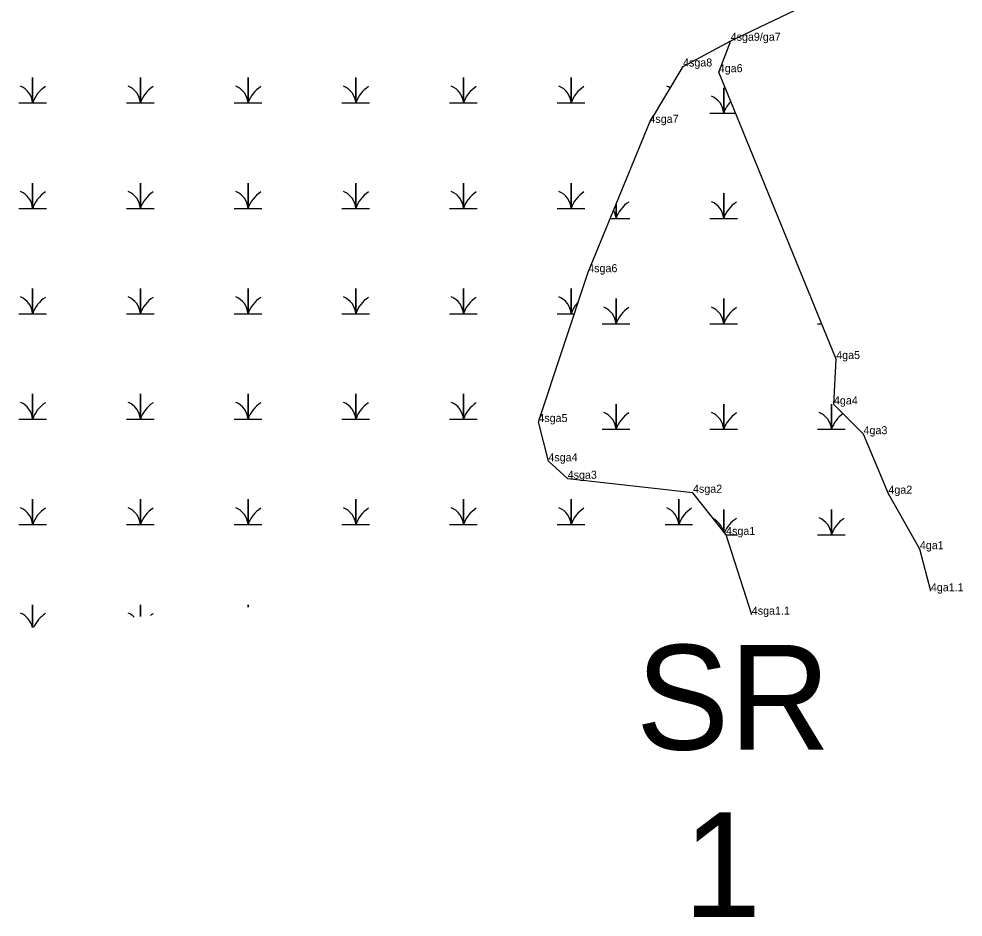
# Model space of a CAD drawing. Extents: x 2072529 to 2268796, y 436423 to 470406.
# Drawn here: x 2105482 to 2106072, y 455709 to 456270 of the extents above; entities that cross this region are included whole.
import ezdxf

# ---------------------------------------------------------------- set-up
doc = ezdxf.new("R2010")
doc.units = 0
for name, color, linetype in [('Default', 7, 'Continuous'), ('Exist Environmental Wetland Boundary', 7, 'Continuous'), ('Exist Environmental Wetland Boundary Cogo Comment', 7, 'Continuous'), ('Exist Hydro Jurisdictional Stream or Body of Water NEU Mitigable', 7, 'Continuous'), ('Exist Hydro Jurisdictional Stream or Body of Water NEU Mitigable Cogo Comment', 7, 'Continuous'), ('Exist Hydro Swamp or Marsh', 7, 'Continuous'), ('Old_Level_20', 7, 'Continuous')]:
    doc.layers.add(name, color=color, linetype=linetype)

msp = doc.modelspace()

# ---------------------------------------------------------------- linework, layer by layer
at = {"layer": 'Exist Environmental Wetland Boundary'}
msp.add_lwpolyline([(2106051.8, 455912.41), (2106044.92, 455938.66), (2106025.27, 455973.29), (2106009.75, 456010.43), (2105991.25, 456029.05), (2105992.67, 456057.36), (2105919.34, 456236.39), (2105926.77, 456256)], dxfattribs=at)
at = {"layer": 'Exist Hydro Jurisdictional Stream or Body of Water NEU Mitigable'}
msp.add_lwpolyline([(2105939.94, 455897.77), (2105923.9, 455947.53), (2105903.24, 455973.88), (2105824.98, 455982.61), (2105812.94, 455993.51), (2105806.67, 456018.05), (2105837.8, 456111.54), (2105876.03, 456204.78), (2105897.03, 456239.95), (2105926.77, 456256), (2105976.18, 456279.56), (2106062.28, 456297.21)], dxfattribs=at)
at = {"layer": 'Exist Hydro Swamp or Marsh'}
for points in [[(2105482.26, 456217.21), (2105490.86, 456217.21), (2105490.86, 456232.99), (2105490.86, 456217.21), (2105499.47, 456217.21)], [(2105549.51, 456217.21), (2105558.11, 456217.21), (2105558.11, 456232.99), (2105558.11, 456217.21), (2105566.72, 456217.21)], [(2105616.76, 456217.21), (2105625.36, 456217.21), (2105625.36, 456232.99), (2105625.36, 456217.21), (2105633.97, 456217.21)], [(2105684.01, 456217.21), (2105692.61, 456217.21), (2105692.61, 456232.99), (2105692.61, 456217.21), (2105701.22, 456217.21)], [(2105751.26, 456217.21), (2105759.86, 456217.21), (2105759.86, 456232.99), (2105759.86, 456217.21), (2105768.47, 456217.21)], [(2105818.51, 456217.21), (2105827.11, 456217.21), (2105827.11, 456232.99), (2105827.11, 456217.21), (2105835.72, 456217.21)], [(2105913.81, 456210.88), (2105922.41, 456210.88), (2105922.41, 456226.66), (2105922.41, 456210.88), (2105929.79, 456210.88)], [(2105482.26, 456151.41), (2105490.86, 456151.41), (2105490.86, 456167.19), (2105490.86, 456151.41), (2105499.47, 456151.41)], [(2105549.51, 456151.41), (2105558.11, 456151.41), (2105558.11, 456167.19), (2105558.11, 456151.41), (2105566.72, 456151.41)], [(2105616.76, 456151.41), (2105625.36, 456151.41), (2105625.36, 456167.19), (2105625.36, 456151.41), (2105633.97, 456151.41)], [(2105684.01, 456151.41), (2105692.61, 456151.41), (2105692.61, 456167.19), (2105692.61, 456151.41), (2105701.22, 456151.41)], [(2105751.26, 456151.41), (2105759.86, 456151.41), (2105759.86, 456167.19), (2105759.86, 456151.41), (2105768.47, 456151.41)], [(2105818.51, 456151.41), (2105827.11, 456151.41), (2105827.11, 456167.19), (2105827.11, 456151.41), (2105835.72, 456151.41)], [(2105913.81, 456145.08), (2105922.41, 456145.08), (2105922.41, 456160.86), (2105922.41, 456145.08), (2105931.01, 456145.08)], [(2105851.55, 456145.08), (2105855.16, 456145.08), (2105855.16, 456153.89)], [(2105855.16, 456153.89), (2105855.16, 456145.08), (2105863.76, 456145.08)], [(2105482.26, 456085.61), (2105490.86, 456085.61), (2105490.86, 456101.39), (2105490.86, 456085.61), (2105499.47, 456085.61)], [(2105549.51, 456085.61), (2105558.11, 456085.61), (2105558.11, 456101.39), (2105558.11, 456085.61), (2105566.72, 456085.61)], [(2105616.76, 456085.61), (2105625.36, 456085.61), (2105625.36, 456101.39), (2105625.36, 456085.61), (2105633.97, 456085.61)], [(2105684.01, 456085.61), (2105692.61, 456085.61), (2105692.61, 456101.39), (2105692.61, 456085.61), (2105701.22, 456085.61)], [(2105751.26, 456085.61), (2105759.86, 456085.61), (2105759.86, 456101.39), (2105759.86, 456085.61), (2105768.47, 456085.61)], [(2105818.51, 456085.61), (2105827.11, 456085.61), (2105827.11, 456101.39), (2105827.11, 456085.61), (2105829.16, 456085.61)], [(2105846.56, 456079.28), (2105855.16, 456079.28), (2105855.16, 456095.06), (2105855.16, 456079.28), (2105863.76, 456079.28)], [(2105913.81, 456079.28), (2105922.41, 456079.28), (2105922.41, 456095.06), (2105922.41, 456079.28), (2105931.01, 456079.28)], [(2105981.06, 456079.28), (2105983.69, 456079.28)], [(2105482.26, 456019.81), (2105490.86, 456019.81), (2105490.86, 456035.59), (2105490.86, 456019.81), (2105499.47, 456019.81)], [(2105549.51, 456019.81), (2105558.11, 456019.81), (2105558.11, 456035.59), (2105558.11, 456019.81), (2105566.72, 456019.81)], [(2105616.76, 456019.81), (2105625.36, 456019.81), (2105625.36, 456035.59), (2105625.36, 456019.81), (2105633.97, 456019.81)], [(2105684.01, 456019.81), (2105692.61, 456019.81), (2105692.61, 456035.59), (2105692.61, 456019.81), (2105701.22, 456019.81)], [(2105751.26, 456019.81), (2105759.86, 456019.81), (2105759.86, 456035.59), (2105759.86, 456019.81), (2105768.47, 456019.81)], [(2105846.56, 456013.48), (2105855.16, 456013.48), (2105855.16, 456029.26), (2105855.16, 456013.48), (2105863.76, 456013.48)], [(2105913.81, 456013.48), (2105922.41, 456013.48), (2105922.41, 456029.26), (2105922.41, 456013.48), (2105931.01, 456013.48)], [(2105981.06, 456013.48), (2105989.66, 456013.48), (2105989.66, 456029.26), (2105989.66, 456013.48), (2105998.26, 456013.48)], [(2105482.26, 455954.01), (2105490.86, 455954.01), (2105490.86, 455969.79), (2105490.86, 455954.01), (2105499.47, 455954.01)], [(2105549.51, 455954.01), (2105558.11, 455954.01), (2105558.11, 455969.79), (2105558.11, 455954.01), (2105566.72, 455954.01)], [(2105616.76, 455954.01), (2105625.36, 455954.01), (2105625.36, 455969.79), (2105625.36, 455954.01), (2105633.97, 455954.01)], [(2105684.01, 455954.01), (2105692.61, 455954.01), (2105692.61, 455969.79), (2105692.61, 455954.01), (2105701.22, 455954.01)], [(2105751.26, 455954.01), (2105759.86, 455954.01), (2105759.86, 455969.79), (2105759.86, 455954.01), (2105768.47, 455954.01)], [(2105818.51, 455954.01), (2105827.11, 455954.01), (2105827.11, 455969.79), (2105827.11, 455954.01), (2105835.72, 455954.01)], [(2105885.76, 455954.01), (2105894.36, 455954.01), (2105894.36, 455969.79), (2105894.36, 455954.01), (2105902.97, 455954.01)], [(2105922.41, 455949.43), (2105922.41, 455963.46), (2105922.41, 455949.43)], [(2105981.06, 455947.68), (2105989.66, 455947.68), (2105989.66, 455963.46), (2105989.66, 455947.68), (2105998.26, 455947.68)], [(2105923.78, 455947.68), (2105931.01, 455947.68)], [(2105490.86, 455889.74), (2105490.86, 455903.99), (2105490.86, 455889.74)], [(2105558.11, 455896.67), (2105558.11, 455903.99), (2105558.11, 455896.67)], [(2105625.36, 455902.54), (2105625.36, 455903.99), (2105625.36, 455902.54)]]:
    msp.add_lwpolyline(points, dxfattribs=at)
for centre, radius, start, end in [((2105478.6, 456216.32), 12.3, 4.14034, 67.53497), ((2105509.11, 456211.15), 19.22, 122.12745, 161.62219), ((2105545.85, 456216.32), 12.3, 4.14034, 67.53497), ((2105576.36, 456211.15), 19.22, 122.12745, 161.62219), ((2105613.1, 456216.32), 12.3, 4.14034, 67.53497), ((2105643.61, 456211.15), 19.22, 122.12745, 161.62219), ((2105680.35, 456216.32), 12.3, 4.14034, 67.53497), ((2105710.86, 456211.15), 19.22, 122.12745, 161.62219), ((2105747.6, 456216.32), 12.3, 4.14034, 67.53497), ((2105778.11, 456211.15), 19.22, 122.12745, 161.62219), ((2105814.85, 456216.32), 12.3, 4.14034, 67.53497), ((2105845.36, 456211.15), 19.22, 122.12745, 161.62219), ((2105882.1, 456216.32), 12.3, 55.8807, 67.53497), ((2105910.15, 456209.99), 12.3, 4.14034, 67.53497), ((2105940.66, 456204.82), 19.22, 136.07388, 161.62219), ((2105478.6, 456150.52), 12.3, 4.14034, 67.53497), ((2105509.11, 456145.35), 19.22, 122.12745, 161.62219), ((2105545.85, 456150.52), 12.3, 4.14034, 67.53497), ((2105576.36, 456145.35), 19.22, 122.12745, 161.62219), ((2105613.1, 456150.52), 12.3, 4.14034, 67.53497), ((2105643.61, 456145.35), 19.22, 122.12745, 161.62219), ((2105680.35, 456150.52), 12.3, 4.14034, 67.53497), ((2105710.86, 456145.35), 19.22, 122.12745, 161.62219), ((2105747.6, 456150.52), 12.3, 4.14034, 67.53497), ((2105778.11, 456145.35), 19.22, 122.12745, 161.62219), ((2105814.85, 456150.52), 12.3, 4.14034, 67.53497), ((2105845.36, 456145.35), 19.22, 122.12745, 161.62219), ((2105873.41, 456139.02), 19.22, 122.12745, 161.62219), ((2105910.15, 456144.19), 12.3, 4.14034, 67.53497), ((2105940.66, 456139.02), 19.22, 122.12745, 161.62219), ((2105842.9, 456144.19), 12.3, 4.14034, 29.12355), ((2105478.6, 456084.72), 12.3, 4.14034, 67.53497), ((2105509.11, 456079.55), 19.22, 122.12745, 161.62219), ((2105545.85, 456084.72), 12.3, 4.14034, 67.53497), ((2105576.36, 456079.55), 19.22, 122.12745, 161.62219), ((2105613.1, 456084.72), 12.3, 4.14034, 67.53497), ((2105643.61, 456079.55), 19.22, 122.12745, 161.62219), ((2105680.35, 456084.72), 12.3, 4.14034, 67.53497), ((2105710.86, 456079.55), 19.22, 122.12745, 161.62219), ((2105747.6, 456084.72), 12.3, 4.14034, 67.53497), ((2105778.11, 456079.55), 19.22, 122.12745, 161.62219), ((2105814.85, 456084.72), 12.3, 4.14034, 67.53497), ((2105845.36, 456079.55), 19.22, 135.59604, 161.62219), ((2105842.9, 456078.39), 12.3, 4.14034, 67.53497), ((2105873.41, 456073.22), 19.22, 122.12745, 161.62219), ((2105910.15, 456078.39), 12.3, 4.14034, 67.53497), ((2105940.66, 456073.22), 19.22, 122.12745, 161.62219), ((2105478.6, 456018.92), 12.3, 4.14034, 67.53497), ((2105509.11, 456013.75), 19.22, 122.12745, 161.62219), ((2105545.85, 456018.92), 12.3, 4.14034, 67.53497), ((2105576.36, 456013.75), 19.22, 122.12745, 161.62219), ((2105613.1, 456018.92), 12.3, 4.14034, 67.53497), ((2105643.61, 456013.75), 19.22, 122.12745, 161.62219), ((2105680.35, 456018.92), 12.3, 4.14034, 67.53497), ((2105710.86, 456013.75), 19.22, 122.12745, 161.62219), ((2105747.6, 456018.92), 12.3, 4.14034, 67.53497), ((2105778.11, 456013.75), 19.22, 122.12745, 161.62219), ((2105842.9, 456012.59), 12.3, 4.14034, 67.53497), ((2105873.41, 456007.42), 19.22, 122.12745, 161.62219), ((2105910.15, 456012.59), 12.3, 4.14034, 67.53497), ((2105940.66, 456007.42), 19.22, 122.12745, 161.62219), ((2105977.4, 456012.59), 12.3, 4.14034, 67.53497), ((2106007.91, 456007.42), 19.22, 124.52348, 161.62219), ((2105478.6, 455953.12), 12.3, 4.14034, 67.53497), ((2105509.11, 455947.95), 19.22, 122.12745, 161.62219), ((2105545.85, 455953.12), 12.3, 4.14034, 67.53497), ((2105576.36, 455947.95), 19.22, 122.12745, 161.62219), ((2105613.1, 455953.12), 12.3, 4.14034, 67.53497), ((2105643.61, 455947.95), 19.22, 122.12745, 161.62219), ((2105680.35, 455953.12), 12.3, 4.14034, 67.53497), ((2105710.86, 455947.95), 19.22, 122.12745, 161.62219), ((2105747.6, 455953.12), 12.3, 4.14034, 67.53497), ((2105778.11, 455947.95), 19.22, 122.12745, 161.62219), ((2105814.85, 455953.12), 12.3, 4.14034, 67.53497), ((2105845.36, 455947.95), 19.22, 122.12745, 161.62219), ((2105882.1, 455953.12), 12.3, 4.14034, 67.53497), ((2105912.61, 455947.95), 19.22, 122.12745, 161.62219), ((2105910.15, 455946.79), 12.3, 14.60347, 61.57684), ((2105940.66, 455941.62), 19.22, 122.12745, 157.84839), ((2105977.4, 455946.79), 12.3, 4.14034, 67.53497), ((2106007.91, 455941.62), 19.22, 122.12745, 161.62219), ((2105478.6, 455887.32), 12.3, 11.25454, 67.53497), ((2105545.85, 455887.32), 12.3, 46.72062, 67.53497), ((2105509.11, 455882.15), 19.22, 122.12745, 156.52673), ((2105576.36, 455882.15), 19.22, 122.12745, 128.13164)]:
    msp.add_arc(centre, radius, start, end, dxfattribs=at)
at = {"layer": 'Old_Level_20'}
for p, q in [((2105926.77, 456256), (2105926.77, 456256)), ((2105926.77, 456256), (2105926.77, 456256)), ((2105897.03, 456239.95), (2105897.03, 456239.95)), ((2105919.34, 456236.39), (2105919.34, 456236.39)), ((2105876.03, 456204.78), (2105876.03, 456204.78)), ((2105837.8, 456111.54), (2105837.8, 456111.54)), ((2105992.67, 456057.36), (2105992.67, 456057.36)), ((2105991.25, 456029.05), (2105991.25, 456029.05)), ((2105806.67, 456018.05), (2105806.67, 456018.05)), ((2106009.75, 456010.43), (2106009.75, 456010.43)), ((2105812.94, 455993.51), (2105812.94, 455993.51)), ((2105824.98, 455982.61), (2105824.98, 455982.61)), ((2105903.24, 455973.88), (2105903.24, 455973.88)), ((2106025.27, 455973.29), (2106025.27, 455973.29)), ((2105923.9, 455947.53), (2105923.9, 455947.53)), ((2106044.92, 455938.66), (2106044.92, 455938.66)), ((2106051.8, 455912.41), (2106051.8, 455912.41)), ((2105939.94, 455897.77), (2105939.94, 455897.77)), ((2105939.94, 455897.77), (2105939.94, 455897.77)), ((2105939.94, 455897.77), (2105939.94, 455897.77))]:
    msp.add_line(p, q, dxfattribs=at)

# ---------------------------------------------------------------- texts
at = {"layer": 'Default'}
for s, p in [('SR', (2105867.61, 455813.54)), ('1', (2105897.17, 455709))]:
    msp.add_text(s, height=65.34, dxfattribs=at).set_placement(p)
at = {"layer": 'Exist Environmental Wetland Boundary Cogo Comment'}
for s, p in [('4ga5', (2105992.67, 456057.36)), ('4ga4', (2105991.25, 456029.05)), ('4ga3', (2106009.75, 456010.43)), ('4ga2', (2106025.27, 455973.29)), ('4ga1', (2106044.92, 455938.66)), ('4ga1.1', (2106051.8, 455912.41))]:
    msp.add_text(s, height=5, dxfattribs=at).set_placement(p)
at = {"layer": 'Exist Hydro Jurisdictional Stream or Body of Water NEU Mitigable Cogo Comment'}
for s, p in [('4sga9/ga7', (2105926.77, 456256)), ('4sga9', (2105926.77, 456256)), ('4sga8', (2105897.03, 456239.95)), ('4ga6', (2105919.34, 456236.39)), ('4sga7', (2105876.03, 456204.78)), ('4sga6', (2105837.8, 456111.54)), ('4sga5', (2105806.67, 456018.05)), ('4sga4', (2105812.94, 455993.51)), ('4sga3', (2105824.98, 455982.61)), ('4sga2', (2105903.24, 455973.88)), ('4sga1', (2105923.9, 455947.53)), ('4sga1.1', (2105939.94, 455897.77))]:
    msp.add_text(s, height=5, dxfattribs=at).set_placement(p)

doc.saveas('drawing.dxf')
